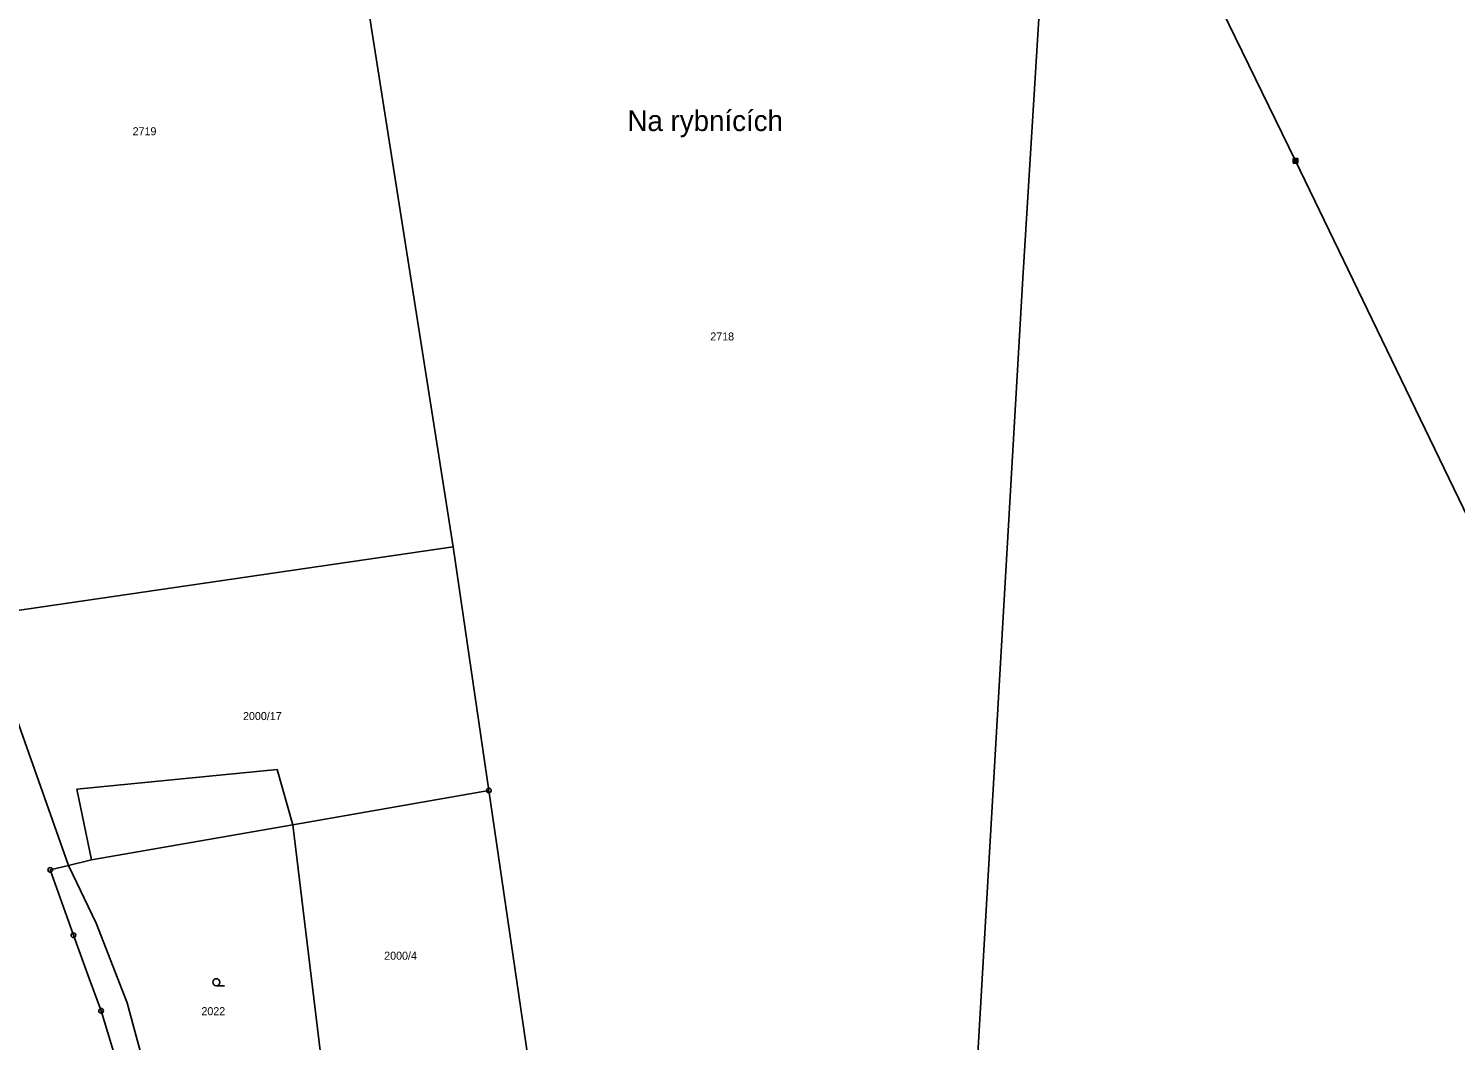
# Model space of a CAD drawing. Extents: x -504988 to -494607, y -1123820 to -1114018.
# Drawn here: x -496283.9 to -495980.9, y -1120435.2 to -1120220.2 of the extents above; entities that cross this region are included whole.
import ezdxf

# ---------------------------------------------------------------- set-up
doc = ezdxf.new("R2010")
doc.units = 0
for name, color, linetype in [('Hranice parcel', 7, 'Continuous'), ('Parcelní čísla', 7, 'Continuous'), ('Pop  PČ popisy', 7, 'Continuous'), ('Poz předměty', 7, 'Continuous'), ('Vnitřní kresba', 7, 'Continuous'), ('Značky bodu BP', 7, 'Continuous'), ('Značky kultur', 7, 'Continuous')]:
    doc.layers.add(name, color=color, linetype=linetype)

msp = doc.modelspace()

# ---------------------------------------------------------------- linework, layer by layer
at = {"layer": 'Hranice parcel'}
for p, q in [((-496224.77, -1120133.29), (-496193.74, -1120330.32)), ((-496072.78, -1120273.25), (-496064.26, -1120136.25)), ((-496082.49, -1120440.4), (-496072.78, -1120273.25)), ((-496193.74, -1120330.32), (-496294.22, -1120344.97)), ((-496193.74, -1120330.32), (-496186.16, -1120382.03)), ((-496292.07, -1120351.04), (-496275.45, -1120397.99)), ((-496186.16, -1120382.03), (-496227.83, -1120389.32)), ((-496186.16, -1120382.03), (-496176.47, -1120448.12)), ((-496227.83, -1120389.32), (-496220.07, -1120452.97))]:
    msp.add_line(p, q, dxfattribs=at)
for points in [[(-496275.45, -1120397.99), (-496270.58, -1120396.8), (-496227.83, -1120389.32)], [(-496275.45, -1120397.99), (-496279.34, -1120398.94), (-496274.41, -1120412.79), (-496271.05, -1120421.96), (-496268.53, -1120428.84), (-496259.6, -1120458.34), (-496260.47, -1120466.26), (-496261.65, -1120483.85), (-496258.97, -1120520.57)], [(-496249.74, -1120456.86), (-496254.8, -1120457.52), (-496262.99, -1120427.16), (-496269.54, -1120410.24), (-496275.45, -1120397.99)]]:
    msp.add_lwpolyline(points, dxfattribs=at)
at = {"layer": 'Poz předměty'}
for p, q in [((-496014.87, -1120248.32), (-496154.23, -1119961.74)), ((-496015.37, -1120247.82), (-496014.37, -1120247.82)), ((-496015.37, -1120248.82), (-496015.37, -1120247.82)), ((-496015.37, -1120248.02), (-496014.37, -1120248.02)), ((-496015.37, -1120248.22), (-496014.37, -1120248.22)), ((-496015.37, -1120248.42), (-496014.37, -1120248.42)), ((-496015.37, -1120248.62), (-496014.37, -1120248.62)), ((-496015.37, -1120248.82), (-496014.37, -1120248.82)), ((-496015.17, -1120248.82), (-496015.17, -1120247.82)), ((-496014.97, -1120248.82), (-496014.97, -1120247.82)), ((-495880.66, -1120526.19), (-496014.87, -1120248.32)), ((-496014.77, -1120248.82), (-496014.77, -1120247.82)), ((-496014.57, -1120248.82), (-496014.57, -1120247.82)), ((-496014.37, -1120248.82), (-496014.37, -1120247.82))]:
    msp.add_line(p, q, dxfattribs=at)
at = {"layer": 'Vnitřní kresba'}
for p, q in [((-496273.68, -1120381.76), (-496231.14, -1120377.61)), ((-496231.14, -1120377.61), (-496227.83, -1120389.32)), ((-496270.58, -1120396.8), (-496273.68, -1120381.76))]:
    msp.add_line(p, q, dxfattribs=at)
at = {"layer": 'Značky bodu BP'}
for centre, radius in [((-496186.16, -1120382.03), 0.5), ((-496186.16, -1120382.03), 0.0303), ((-496279.34, -1120398.94), 0.5), ((-496279.34, -1120398.94), 0.0303), ((-496274.41, -1120412.79), 0.5), ((-496274.41, -1120412.79), 0.0303), ((-496268.53, -1120428.84), 0.5), ((-496268.53, -1120428.84), 0.0303)]:
    msp.add_circle(centre, radius, dxfattribs=at)
at = {"layer": 'Značky kultur'}
msp.add_line((-496244.04, -1120423.53), (-496242.29, -1120423.53), dxfattribs=at)
msp.add_circle((-496244.04, -1120422.78), 0.75, dxfattribs=at)

# ---------------------------------------------------------------- texts
at = {"layer": 'Parcelní čísla'}
for s, p in [('2719', (-496261.83, -1120242.89)), ('2718', (-496139.14, -1120286.48)), ('2000/17', (-496238.38, -1120367.1)), ('2000/4', (-496208.4, -1120418)), ('2022', (-496247.22, -1120429.78))]:
    msp.add_text(s, height=1.7, dxfattribs=at).set_placement(p)
at = {"layer": 'Pop  PČ popisy'}
msp.add_text('Na rybnících', height=4.4, dxfattribs=at).set_placement((-496156.73, -1120242))

doc.saveas('drawing.dxf')
